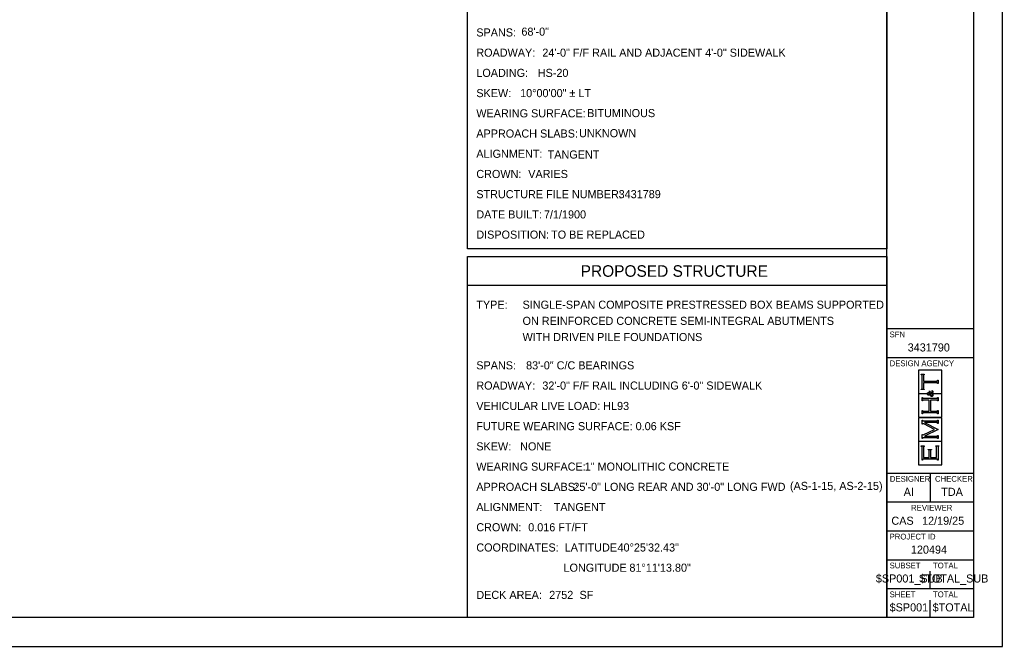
# Model space of a CAD drawing. Extents: x 0 to 34, y 0 to 22.
# Drawn here: x 17 to 34, y 0 to 10.85 of the extents above; entities that cross this region are included whole.
import ezdxf

# ---------------------------------------------------------------- set-up
doc = ezdxf.new("R2010")
doc.units = 0
for name, color, linetype in [('BR_X_Slab_Object', 7, 'Continuous'), ('DR_X_Drive_Pipe', 7, 'Continuous'), ('GM_X_Rail_Line', 7, 'Continuous')]:
    doc.layers.add(name, color=color, linetype=linetype)

msp = doc.modelspace()

# ---------------------------------------------------------------- linework, layer by layer
at = {"layer": 'BR_X_Slab_Object'}
msp.add_lwpolyline([(0, 0), (34, 0), (34, 22), (0, 22)], close=True, dxfattribs=at)
at = {"layer": 'DR_X_Drive_Pipe'}
for p, q in [((32, 6.248), (24.75, 6.248)), ((32.952, 4.779), (32.547, 4.779)), ((32.547, 4.779), (32.547, 4.375)), ((32.952, 4.375), (32.952, 4.779)), ((32.598, 4.704), (32.598, 4.711)), ((32.598, 4.711), (32.65, 4.711)), ((32.603, 4.703), (32.598, 4.704)), ((32.606, 4.701), (32.603, 4.703)), ((32.608, 4.699), (32.606, 4.701)), ((32.61, 4.696), (32.608, 4.699)), ((32.611, 4.692), (32.61, 4.696)), ((32.611, 4.687), (32.611, 4.692)), ((32.611, 4.468), (32.611, 4.687)), ((32.638, 4.696), (32.637, 4.692)), ((32.637, 4.692), (32.637, 4.687)), ((32.637, 4.687), (32.637, 4.593)), ((32.637, 4.593), (32.864, 4.593)), ((32.64, 4.699), (32.638, 4.696)), ((32.642, 4.701), (32.64, 4.699)), ((32.645, 4.703), (32.642, 4.701)), ((32.65, 4.704), (32.645, 4.703)), ((32.65, 4.711), (32.65, 4.704)), ((32.864, 4.593), (32.869, 4.593)), ((32.869, 4.593), (32.873, 4.594)), ((32.873, 4.594), (32.876, 4.596)), ((32.876, 4.596), (32.878, 4.597)), ((32.878, 4.597), (32.88, 4.601)), ((32.88, 4.601), (32.881, 4.606)), ((32.881, 4.606), (32.888, 4.606)), ((32.888, 4.606), (32.888, 4.548)), ((32.598, 4.45), (32.603, 4.451)), ((32.598, 4.444), (32.598, 4.45)), ((32.65, 4.444), (32.598, 4.444)), ((32.603, 4.451), (32.606, 4.453)), ((32.606, 4.453), (32.608, 4.455)), ((32.608, 4.455), (32.61, 4.458)), ((32.61, 4.458), (32.611, 4.462)), ((32.611, 4.462), (32.611, 4.468)), ((32.864, 4.561), (32.637, 4.561)), ((32.637, 4.561), (32.637, 4.468)), ((32.637, 4.468), (32.637, 4.462)), ((32.637, 4.462), (32.638, 4.458)), ((32.638, 4.458), (32.64, 4.455)), ((32.64, 4.455), (32.642, 4.453)), ((32.642, 4.453), (32.645, 4.451)), ((32.645, 4.451), (32.65, 4.45)), ((32.65, 4.45), (32.65, 4.444)), ((32.738, 4.393), (32.738, 4.422)), ((32.738, 4.422), (32.741, 4.422)), ((32.741, 4.422), (32.741, 4.418)), ((32.779, 4.423), (32.781, 4.426)), ((32.782, 4.422), (32.779, 4.423)), ((32.781, 4.426), (32.787, 4.424)), ((32.785, 4.421), (32.782, 4.422)), ((32.786, 4.419), (32.785, 4.421)), ((32.787, 4.424), (32.792, 4.421)), ((32.792, 4.421), (32.795, 4.418)), ((32.87, 4.561), (32.864, 4.561)), ((32.874, 4.56), (32.87, 4.561)), ((32.876, 4.559), (32.874, 4.56)), ((32.878, 4.557), (32.876, 4.559)), ((32.88, 4.553), (32.878, 4.557)), ((32.881, 4.548), (32.88, 4.553)), ((32.888, 4.548), (32.881, 4.548)), ((32.547, 4.375), (32.696, 4.375)), ((32.696, 4.369), (32.547, 4.369)), ((32.547, 4.369), (32.547, 3.965)), ((32.611, 4.249), (32.611, 4.307)), ((32.611, 4.307), (32.617, 4.307)), ((32.617, 4.307), (32.619, 4.302)), ((32.618, 4.254), (32.617, 4.249)), ((32.62, 4.258), (32.618, 4.254)), ((32.619, 4.302), (32.62, 4.298)), ((32.62, 4.298), (32.623, 4.297)), ((32.623, 4.26), (32.62, 4.258)), ((32.623, 4.297), (32.625, 4.295)), ((32.625, 4.261), (32.623, 4.26)), ((32.625, 4.295), (32.629, 4.294)), ((32.629, 4.262), (32.625, 4.261)), ((32.629, 4.294), (32.635, 4.294)), ((32.635, 4.262), (32.629, 4.262)), ((32.635, 4.294), (32.864, 4.294)), ((32.732, 4.262), (32.635, 4.262)), ((32.696, 4.375), (32.696, 4.369)), ((32.703, 4.379), (32.705, 4.383)), ((32.703, 4.373), (32.703, 4.379)), ((32.703, 4.368), (32.703, 4.373)), ((32.705, 4.363), (32.703, 4.368)), ((32.705, 4.383), (32.708, 4.387)), ((32.708, 4.358), (32.705, 4.363)), ((32.708, 4.387), (32.711, 4.39)), ((32.709, 4.379), (32.708, 4.376)), ((32.708, 4.376), (32.708, 4.373)), ((32.708, 4.373), (32.708, 4.369)), ((32.708, 4.369), (32.71, 4.366)), ((32.712, 4.353), (32.708, 4.358)), ((32.712, 4.381), (32.709, 4.379)), ((32.71, 4.366), (32.712, 4.364)), ((32.711, 4.39), (32.715, 4.392)), ((32.714, 4.383), (32.712, 4.381)), ((32.712, 4.364), (32.715, 4.362)), ((32.718, 4.35), (32.712, 4.353)), ((32.716, 4.384), (32.714, 4.383)), ((32.715, 4.392), (32.72, 4.392)), ((32.715, 4.362), (32.718, 4.361)), ((32.72, 4.384), (32.716, 4.384)), ((32.718, 4.361), (32.721, 4.361)), ((32.726, 4.35), (32.718, 4.35)), ((32.72, 4.392), (32.725, 4.392)), ((32.724, 4.384), (32.72, 4.384)), ((32.721, 4.361), (32.723, 4.361)), ((32.723, 4.361), (32.725, 4.362)), ((32.728, 4.382), (32.724, 4.384)), ((32.725, 4.392), (32.729, 4.39)), ((32.725, 4.362), (32.728, 4.362)), ((32.729, 4.35), (32.726, 4.35)), ((32.731, 4.38), (32.728, 4.382)), ((32.728, 4.362), (32.731, 4.363)), ((32.729, 4.39), (32.732, 4.387)), ((32.731, 4.35), (32.729, 4.35)), ((32.734, 4.377), (32.731, 4.38)), ((32.731, 4.363), (32.735, 4.365)), ((32.734, 4.351), (32.731, 4.35)), ((32.732, 4.387), (32.736, 4.383)), ((32.732, 4.072), (32.732, 4.262)), ((32.737, 4.372), (32.734, 4.377)), ((32.737, 4.352), (32.734, 4.351)), ((32.735, 4.365), (32.74, 4.367)), ((32.736, 4.383), (32.74, 4.378)), ((32.74, 4.367), (32.737, 4.372)), ((32.741, 4.353), (32.737, 4.352)), ((32.741, 4.393), (32.738, 4.393)), ((32.74, 4.378), (32.744, 4.369)), ((32.741, 4.418), (32.742, 4.415)), ((32.742, 4.396), (32.741, 4.395)), ((32.741, 4.395), (32.741, 4.393)), ((32.746, 4.355), (32.741, 4.353)), ((32.742, 4.415), (32.743, 4.413)), ((32.743, 4.397), (32.742, 4.396)), ((32.743, 4.413), (32.745, 4.411)), ((32.745, 4.399), (32.743, 4.397)), ((32.744, 4.369), (32.754, 4.375)), ((32.745, 4.411), (32.749, 4.408)), ((32.746, 4.399), (32.745, 4.399)), ((32.748, 4.399), (32.746, 4.399)), ((32.752, 4.344), (32.746, 4.355)), ((32.755, 4.399), (32.748, 4.399)), ((32.749, 4.408), (32.756, 4.404)), ((32.756, 4.36), (32.751, 4.357)), ((32.751, 4.357), (32.754, 4.352)), ((32.757, 4.337), (32.752, 4.344)), ((32.754, 4.375), (32.764, 4.381)), ((32.754, 4.352), (32.757, 4.348)), ((32.763, 4.395), (32.755, 4.399)), ((32.756, 4.404), (32.763, 4.4)), ((32.761, 4.363), (32.756, 4.36)), ((32.757, 4.348), (32.761, 4.345)), ((32.763, 4.333), (32.757, 4.337)), ((32.864, 4.262), (32.759, 4.262)), ((32.759, 4.262), (32.759, 4.072)), ((32.764, 4.365), (32.761, 4.363)), ((32.761, 4.345), (32.765, 4.343)), ((32.763, 4.4), (32.77, 4.396)), ((32.772, 4.387), (32.763, 4.395)), ((32.768, 4.329), (32.763, 4.333)), ((32.764, 4.381), (32.772, 4.387)), ((32.768, 4.367), (32.764, 4.365)), ((32.765, 4.343), (32.769, 4.341)), ((32.774, 4.372), (32.768, 4.367)), ((32.774, 4.327), (32.768, 4.329)), ((32.769, 4.341), (32.773, 4.341)), ((32.77, 4.396), (32.776, 4.391)), ((32.773, 4.341), (32.778, 4.341)), ((32.782, 4.378), (32.774, 4.372)), ((32.779, 4.327), (32.774, 4.327)), ((32.776, 4.391), (32.781, 4.395)), ((32.778, 4.341), (32.782, 4.343)), ((32.785, 4.327), (32.779, 4.327)), ((32.781, 4.395), (32.784, 4.398)), ((32.786, 4.373), (32.782, 4.378)), ((32.782, 4.343), (32.786, 4.346)), ((32.784, 4.398), (32.786, 4.401)), ((32.79, 4.329), (32.785, 4.327)), ((32.788, 4.417), (32.786, 4.419)), ((32.786, 4.401), (32.788, 4.404)), ((32.791, 4.386), (32.786, 4.381)), ((32.786, 4.381), (32.791, 4.376)), ((32.788, 4.369), (32.786, 4.373)), ((32.786, 4.346), (32.789, 4.349)), ((32.789, 4.414), (32.788, 4.417)), ((32.788, 4.404), (32.789, 4.408)), ((32.79, 4.367), (32.788, 4.369)), ((32.789, 4.411), (32.789, 4.414)), ((32.789, 4.408), (32.789, 4.411)), ((32.789, 4.349), (32.791, 4.353)), ((32.791, 4.364), (32.79, 4.367)), ((32.793, 4.334), (32.79, 4.329)), ((32.794, 4.39), (32.791, 4.386)), ((32.791, 4.376), (32.795, 4.37)), ((32.791, 4.361), (32.791, 4.364)), ((32.791, 4.359), (32.791, 4.361)), ((32.791, 4.353), (32.791, 4.359)), ((32.797, 4.338), (32.793, 4.334)), ((32.796, 4.394), (32.794, 4.39)), ((32.795, 4.418), (32.798, 4.414)), ((32.795, 4.37), (32.797, 4.366)), ((32.798, 4.397), (32.796, 4.394)), ((32.797, 4.366), (32.798, 4.361)), ((32.799, 4.344), (32.797, 4.338)), ((32.798, 4.414), (32.799, 4.41)), ((32.799, 4.401), (32.798, 4.397)), ((32.798, 4.361), (32.799, 4.357)), ((32.799, 4.41), (32.799, 4.405)), ((32.799, 4.405), (32.799, 4.401)), ((32.803, 4.369), (32.799, 4.375)), ((32.799, 4.375), (32.952, 4.375)), ((32.799, 4.357), (32.799, 4.352)), ((32.799, 4.352), (32.799, 4.344)), ((32.952, 4.369), (32.803, 4.369)), ((32.864, 4.294), (32.869, 4.294)), ((32.87, 4.262), (32.864, 4.262)), ((32.869, 4.294), (32.873, 4.295)), ((32.874, 4.261), (32.87, 4.262)), ((32.873, 4.295), (32.876, 4.297)), ((32.876, 4.26), (32.874, 4.261)), ((32.876, 4.297), (32.878, 4.298)), ((32.878, 4.258), (32.876, 4.26)), ((32.878, 4.298), (32.88, 4.302)), ((32.88, 4.254), (32.878, 4.258)), ((32.88, 4.302), (32.881, 4.307)), ((32.881, 4.249), (32.88, 4.254)), ((32.881, 4.307), (32.888, 4.307)), ((32.888, 4.307), (32.888, 4.249)), ((32.952, 3.965), (32.952, 4.369)), ((32.617, 4.249), (32.611, 4.249)), ((32.611, 4.027), (32.611, 4.085)), ((32.611, 4.085), (32.617, 4.085)), ((32.617, 4.085), (32.619, 4.08)), ((32.88, 4.08), (32.881, 4.085)), ((32.888, 4.249), (32.881, 4.249)), ((32.881, 4.085), (32.888, 4.085)), ((32.888, 4.085), (32.888, 4.027)), ((32.547, 3.965), (32.952, 3.965)), ((32.952, 3.959), (32.547, 3.959)), ((32.547, 3.959), (32.547, 3.555)), ((32.617, 4.027), (32.611, 4.027)), ((32.611, 3.845), (32.611, 3.918)), ((32.611, 3.918), (32.617, 3.918)), ((32.618, 4.032), (32.617, 4.027)), ((32.617, 3.918), (32.619, 3.912)), ((32.62, 4.036), (32.618, 4.032)), ((32.619, 4.08), (32.62, 4.076)), ((32.619, 3.912), (32.62, 3.909)), ((32.62, 4.076), (32.623, 4.074)), ((32.623, 4.037), (32.62, 4.036)), ((32.623, 4.074), (32.625, 4.073)), ((32.625, 4.039), (32.623, 4.037)), ((32.625, 4.073), (32.629, 4.072)), ((32.629, 4.04), (32.625, 4.039)), ((32.629, 4.072), (32.635, 4.072)), ((32.635, 4.04), (32.629, 4.04)), ((32.635, 4.072), (32.732, 4.072)), ((32.864, 4.04), (32.635, 4.04)), ((32.75, 4), (32.75, 4)), ((32.759, 4.072), (32.864, 4.072)), ((32.864, 4.072), (32.87, 4.072)), ((32.87, 4.04), (32.864, 4.04)), ((32.87, 4.072), (32.874, 4.073)), ((32.874, 4.039), (32.87, 4.04)), ((32.874, 4.073), (32.876, 4.074)), ((32.876, 4.038), (32.874, 4.039)), ((32.876, 4.074), (32.878, 4.076)), ((32.878, 4.036), (32.876, 4.038)), ((32.878, 4.076), (32.88, 4.08)), ((32.88, 4.032), (32.878, 4.036)), ((32.878, 3.909), (32.88, 3.912)), ((32.881, 4.027), (32.88, 4.032)), ((32.88, 3.912), (32.881, 3.918)), ((32.888, 4.027), (32.881, 4.027)), ((32.881, 3.918), (32.888, 3.918)), ((32.888, 3.918), (32.888, 3.86)), ((32.952, 3.555), (32.952, 3.959)), ((32.617, 3.845), (32.611, 3.845)), ((32.62, 3.852), (32.617, 3.845)), ((32.62, 3.909), (32.623, 3.907)), ((32.622, 3.855), (32.62, 3.852)), ((32.626, 3.855), (32.622, 3.855)), ((32.623, 3.907), (32.625, 3.905)), ((32.625, 3.905), (32.629, 3.905)), ((32.629, 3.855), (32.626, 3.855)), ((32.629, 3.905), (32.635, 3.905)), ((32.633, 3.853), (32.629, 3.855)), ((32.64, 3.85), (32.633, 3.853)), ((32.635, 3.905), (32.864, 3.905)), ((32.825, 3.757), (32.64, 3.85)), ((32.641, 3.665), (32.825, 3.757)), ((32.864, 3.873), (32.654, 3.873)), ((32.654, 3.873), (32.888, 3.755)), ((32.888, 3.755), (32.654, 3.638)), ((32.864, 3.905), (32.869, 3.905)), ((32.87, 3.873), (32.864, 3.873)), ((32.869, 3.905), (32.873, 3.905)), ((32.874, 3.872), (32.87, 3.873)), ((32.873, 3.905), (32.876, 3.907)), ((32.876, 3.87), (32.874, 3.872)), ((32.876, 3.907), (32.878, 3.909)), ((32.878, 3.869), (32.876, 3.87)), ((32.88, 3.865), (32.878, 3.869)), ((32.881, 3.86), (32.88, 3.865)), ((32.888, 3.86), (32.881, 3.86)), ((32.611, 3.596), (32.611, 3.668)), ((32.611, 3.668), (32.617, 3.668)), ((32.617, 3.596), (32.611, 3.596)), ((32.617, 3.668), (32.62, 3.662)), ((32.618, 3.602), (32.617, 3.596)), ((32.62, 3.605), (32.618, 3.602)), ((32.62, 3.662), (32.622, 3.658)), ((32.623, 3.607), (32.62, 3.605)), ((32.622, 3.658), (32.626, 3.658)), ((32.625, 3.609), (32.623, 3.607)), ((32.629, 3.609), (32.625, 3.609)), ((32.626, 3.658), (32.627, 3.658)), ((32.627, 3.658), (32.633, 3.661)), ((32.635, 3.609), (32.629, 3.609)), ((32.633, 3.661), (32.641, 3.665)), ((32.864, 3.609), (32.635, 3.609)), ((32.654, 3.638), (32.864, 3.638)), ((32.864, 3.638), (32.869, 3.638)), ((32.87, 3.609), (32.864, 3.609)), ((32.869, 3.638), (32.873, 3.639)), ((32.874, 3.609), (32.87, 3.609)), ((32.873, 3.639), (32.876, 3.641)), ((32.876, 3.607), (32.874, 3.609)), ((32.876, 3.641), (32.878, 3.643)), ((32.878, 3.605), (32.876, 3.607)), ((32.878, 3.643), (32.88, 3.646)), ((32.88, 3.602), (32.878, 3.605)), ((32.88, 3.646), (32.881, 3.651)), ((32.881, 3.596), (32.88, 3.602)), ((32.881, 3.651), (32.888, 3.651)), ((32.888, 3.596), (32.881, 3.596)), ((32.888, 3.651), (32.888, 3.596)), ((32.547, 3.555), (32.952, 3.555)), ((32.952, 3.549), (32.547, 3.549)), ((32.547, 3.549), (32.547, 3.145)), ((32.598, 3.462), (32.598, 3.469)), ((32.598, 3.469), (32.65, 3.469)), ((32.603, 3.461), (32.598, 3.462)), ((32.606, 3.459), (32.603, 3.461)), ((32.608, 3.457), (32.606, 3.459)), ((32.61, 3.455), (32.608, 3.457)), ((32.611, 3.451), (32.61, 3.455)), ((32.611, 3.445), (32.611, 3.451)), ((32.611, 3.225), (32.611, 3.445)), ((32.64, 3.457), (32.638, 3.455)), ((32.638, 3.455), (32.638, 3.451)), ((32.638, 3.451), (32.638, 3.445)), ((32.638, 3.445), (32.638, 3.27)), ((32.642, 3.459), (32.64, 3.457)), ((32.645, 3.461), (32.642, 3.459)), ((32.65, 3.462), (32.645, 3.461)), ((32.65, 3.469), (32.65, 3.462)), ((32.719, 3.402), (32.719, 3.408)), ((32.719, 3.408), (32.772, 3.408)), ((32.724, 3.401), (32.719, 3.402)), ((32.728, 3.399), (32.724, 3.401)), ((32.767, 3.401), (32.763, 3.399)), ((32.772, 3.402), (32.767, 3.401)), ((32.772, 3.408), (32.772, 3.402)), ((32.848, 3.465), (32.848, 3.472)), ((32.848, 3.472), (32.901, 3.472)), ((32.853, 3.464), (32.848, 3.465)), ((32.857, 3.462), (32.853, 3.464)), ((32.859, 3.46), (32.857, 3.462)), ((32.86, 3.458), (32.859, 3.46)), ((32.861, 3.453), (32.86, 3.458)), ((32.861, 3.448), (32.861, 3.453)), ((32.861, 3.27), (32.861, 3.448)), ((32.889, 3.457), (32.888, 3.453)), ((32.888, 3.453), (32.888, 3.448)), ((32.888, 3.448), (32.888, 3.225)), ((32.891, 3.46), (32.889, 3.457)), ((32.892, 3.462), (32.891, 3.46)), ((32.896, 3.464), (32.892, 3.462)), ((32.901, 3.465), (32.896, 3.464)), ((32.901, 3.472), (32.901, 3.465)), ((32.952, 3.145), (32.952, 3.549)), ((32.619, 3.23), (32.617, 3.225)), ((32.62, 3.234), (32.619, 3.23)), ((32.623, 3.235), (32.62, 3.234)), ((32.625, 3.237), (32.623, 3.235)), ((32.629, 3.238), (32.625, 3.237)), ((32.635, 3.238), (32.629, 3.238)), ((32.864, 3.238), (32.635, 3.238)), ((32.638, 3.27), (32.732, 3.27)), ((32.729, 3.396), (32.728, 3.399)), ((32.731, 3.394), (32.729, 3.396)), ((32.732, 3.39), (32.731, 3.394)), ((32.732, 3.384), (32.732, 3.39)), ((32.732, 3.27), (32.732, 3.384)), ((32.76, 3.394), (32.759, 3.39)), ((32.759, 3.39), (32.759, 3.384)), ((32.759, 3.384), (32.759, 3.27)), ((32.759, 3.27), (32.861, 3.27)), ((32.761, 3.396), (32.76, 3.394)), ((32.763, 3.399), (32.761, 3.396)), ((32.87, 3.238), (32.864, 3.238)), ((32.874, 3.237), (32.87, 3.238)), ((32.876, 3.235), (32.874, 3.237)), ((32.878, 3.234), (32.876, 3.235)), ((32.88, 3.23), (32.878, 3.234)), ((32.881, 3.225), (32.88, 3.23)), ((32.547, 3.145), (32.952, 3.145)), ((32.617, 3.225), (32.611, 3.225)), ((32.888, 3.225), (32.881, 3.225)), ((32.75, 1), (32.75, 1.3)), ((32.75, 0.5), (32.75, 0.8)), ((32.375, 0.675), (32.375, 0.675))]:
    msp.add_line(p, q, dxfattribs=at)
for points in [[(24.75, 12.498), (32, 12.498), (32, 6.884), (24.75, 6.884)], [(24.75, 6.748), (32, 6.748), (32, 0.5), (24.75, 0.5)]]:
    msp.add_lwpolyline(points, close=True, dxfattribs=at)
at = {"layer": 'GM_X_Rail_Line'}
for p, q in [((32, 0.5), (32, 21.5)), ((32, 5.5), (33.5, 5.5)), ((32, 5), (33.5, 5)), ((32, 3), (33.5, 3)), ((32.75, 3), (32.75, 2.5)), ((32, 2.5), (33.5, 2.5)), ((32, 2), (33.5, 2)), ((32, 1.5), (33.5, 1.5)), ((32, 1), (33.5, 1))]:
    msp.add_line(p, q, dxfattribs=at)
msp.add_lwpolyline([(1.5, 21.5), (33.5, 21.5), (33.5, 0.5), (1.5, 0.5)], close=True, dxfattribs=at)

# ---------------------------------------------------------------- texts
at = {"layer": 'DR_X_Drive_Pipe'}
for s, height, p in [('68\'-0"                                            ', 0.14, (25.68, 10.572)), ('SPANS:', 0.14, (24.9, 10.558)), ('ROADWAY:', 0.14, (24.9, 10.208)), ('24\'-0" F/F RAIL AND ADJACENT 4\'-0" SIDEWALK', 0.14, (26.042, 10.208)), ('LOADING:', 0.14, (24.9, 9.858)), ('HS-20                                       ', 0.14, (25.963, 9.858)), ('SKEW:', 0.14, (24.9, 9.508)), ('10°00\'00" ± LT', 0.14, (25.658, 9.508)), ('WEARING SURFACE:', 0.14, (24.9, 9.158)), ('BITUMINOUS                                  ', 0.14, (26.818, 9.162)), ('APPROACH SLABS:', 0.14, (24.9, 8.808)), ('UNKNOWN', 0.14, (26.677, 8.814)), ('ALIGNMENT:', 0.14, (24.9, 8.458)), ('TANGENT', 0.14, (26.134, 8.445)), ('CROWN:', 0.14, (24.9, 8.108)), ('VARIES', 0.14, (25.798, 8.108)), ('STRUCTURE FILE NUMBER:', 0.14, (24.9, 7.758)), ('3431789     ', 0.14, (27.362, 7.759)), ('DATE BUILT:', 0.14, (24.9, 7.408)), ('7/1/1900    ', 0.14, (26.07, 7.408)), ('DISPOSITION:', 0.14, (24.9, 7.058)), ('TO BE REPLACED                  ', 0.14, (26.194, 7.058)), ('PROPOSED STRUCTURE', 0.2, (26.705, 6.398)), ('TYPE:', 0.14, (24.9, 5.845)), ('SINGLE-SPAN COMPOSITE PRESTRESSED BOX BEAMS SUPPORTED  ', 0.14, (25.7, 5.845)), ('ON REINFORCED CONCRETE SEMI-INTEGRAL ABUTMENTS    ', 0.14, (25.7, 5.565)), ('SFN', 0.1, (32.05, 5.35)), ('WITH DRIVEN PILE FOUNDATIONS                           ', 0.14, (25.7, 5.285)), ('3431790', 0.14, (32.363, 5.105)), ('SPANS:', 0.14, (24.9, 4.795)), ('83\'-0" C/C BEARINGS                               ', 0.14, (25.761, 4.795)), ('DESIGN AGENCY', 0.1, (32.05, 4.85)), ('32\'-0" F/F RAIL INCLUDING 6\'-0" SIDEWALK', 0.14, (26.042, 4.445)), ('ROADWAY:', 0.14, (24.9, 4.445)), ('VEHICULAR LIVE LOAD: HL93', 0.14, (24.9, 4.092)), ('FUTURE WEARING SURFACE: 0.06 KSF', 0.14, (24.9, 3.742)), ('SKEW:', 0.14, (24.9, 3.392)), ('NONE', 0.14, (25.658, 3.392)), ('WEARING SURFACE:', 0.14, (24.9, 3.042)), ('1" MONOLITHIC CONCRETE', 0.14, (26.775, 3.042)), ('DESIGNER', 0.1, (32.054, 2.85)), ('CHECKER', 0.1, (32.835, 2.85)), ('APPROACH SLABS:', 0.14, (24.9, 2.692)), ('25\'-0" LONG REAR AND 30\'-0" LONG FWD  ', 0.14, (26.579, 2.692)), ('(AS-1-15, AS-2-15)', 0.14, (30.326, 2.708)), ('AI', 0.14, (32.293, 2.605)), ('TDA', 0.14, (32.943, 2.605)), ('ALIGNMENT:', 0.14, (24.9, 2.342)), ('TANGENT                     ', 0.14, (26.239, 2.342)), ('REVIEWER', 0.1, (32.422, 2.35)), ('CAS', 0.14, (32.081, 2.105)), ('12/19/25', 0.14, (32.611, 2.105)), ('CROWN:', 0.14, (24.9, 1.992)), ('0.016 FT/FT', 0.14, (25.798, 1.992)), ('PROJECT ID', 0.1, (32.05, 1.85)), ('COORDINATES:  LATITUDE', 0.14, (24.9, 1.642)), ('40°25\'32.43"', 0.14, (27.343, 1.642)), ('120494', 0.14, (32.418, 1.605)), ('                             LONGITUDE', 0.14, (24.9, 1.292)), ('81°11\'13.80"', 0.14, (27.549, 1.292)), ('SUBSET', 0.1, (32.05, 1.35)), ('TOTAL', 0.1, (32.8, 1.35)), ('$SP001_SUB', 0.14, (31.812, 1.105)), ('$TOTAL_SUB', 0.14, (32.562, 1.105)), ('DECK AREA:', 0.14, (24.9, 0.821)), ('2752      ', 0.14, (26.161, 0.821)), ('SF', 0.14, (26.686, 0.821)), ('SHEET', 0.1, (32.05, 0.85)), ('TOTAL', 0.1, (32.8, 0.85)), ('$SP001', 0.14, (32.05, 0.605)), ('$TOTAL', 0.14, (32.794, 0.605))]:
    msp.add_text(s, height=height, dxfattribs=at).set_placement(p)

doc.saveas('drawing.dxf')
